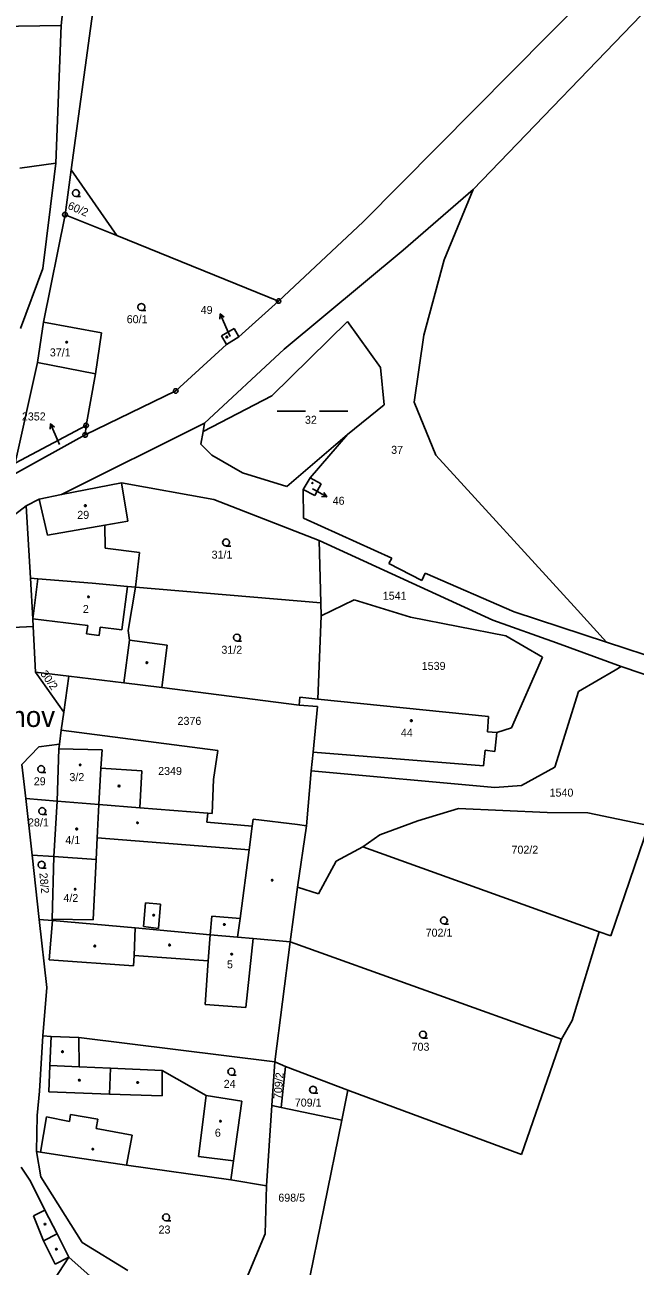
# Model space of a CAD drawing. Extents: x -852001 to -848657, y -1054973 to -1052182.
# Drawn here: x -850612.8 to -850483.1, y -1053593.3 to -1053329.6 of the extents above; entities that cross this region are included whole.
import ezdxf

# ---------------------------------------------------------------- set-up
doc = ezdxf.new("R2010")
doc.units = 0
for name, color, linetype in [('KN_HRANICE', 7, 'Continuous'), ('KN_KULTURY', 7, 'Continuous'), ('KN_MEZNIKY', 7, 'Continuous'), ('KN_PARCELY', 7, 'Continuous'), ('KN_SLUCKY', 7, 'Continuous'), ('KN_STAVEBNI', 7, 'Continuous')]:
    doc.layers.add(name, color=color, linetype=linetype)

# ---------------------------------------------------------------- blocks, each defined once
blk = doc.blocks.new('304')
blk.add_lwpolyline([(0, 0), (-0.38, 0.1), (-0.65, 0.37), (-0.75, 0.74), (-0.65, 1.11), (-0.38, 1.38), (-0.01, 1.48), (0.36, 1.38), (0.63, 1.11), (0.73, 0.73), (0.63, 0.35), (0.36, 0.08), (-0.02, -0.02), (0.98, -0.02)])
blk = doc.blocks.new('NAHRADNI_SYMBOL')
blk.add_lwpolyline([(0.09, 0.15), (0.18, 0), (0.09, -0.15), (-0.09, -0.15), (-0.18, 0), (-0.09, 0.15), (0.09, 0.15)])
blk = doc.blocks.new('803')
for p, q in [((-7.5, 0), (-1.5, 0)), ((1.5, 0), (7.5, 0))]:
    blk.add_line(p, q)
blk = doc.blocks.new('10292')
blk.add_line((0, 3), (0, 0))
blk.add_lwpolyline([(-0.5, 2), (0, 3), (0.5, 2)])
blk = doc.blocks.new('402')
blk.add_lwpolyline([(0.09, 0.15), (0.18, 0), (0.09, -0.15), (-0.09, -0.15), (-0.18, 0), (-0.09, 0.15), (0.09, 0.15)])
blk = doc.blocks.new('105')
blk.add_line((-0.12, 0), (0.12, 0))
blk.add_lwpolyline([(0.15, 0.48), (0.4, 0.3), (0.5, 0.01), (0.4, -0.28), (0.15, -0.46), (-0.16, -0.46), (-0.41, -0.28), (-0.51, 0.01), (-0.41, 0.3), (-0.16, 0.48), (0.15, 0.48)])

msp = doc.modelspace()

# ---------------------------------------------------------------- linework, layer by layer
at = {"layer": 'KN_HRANICE'}
for p, q in [((-850422.36, -1053251.92), (-850540.88, -1053371.46)), ((-850601.94, -1053301.5), (-850605.07, -1053329.74)), ((-850595.22, -1053304.04), (-850602.92, -1053360.4)), ((-850471.08, -1053316.39), (-850517.5, -1053364.63)), ((-850605.07, -1053329.74), (-850649.35, -1053330.52)), ((-850605.07, -1053329.74), (-850606.19, -1053358.98)), ((-850613.8, -1053360.1), (-850606.19, -1053358.98)), ((-850606.19, -1053358.98), (-850606.54, -1053361.94)), ((-850606.54, -1053361.94), (-850608.91, -1053381.35)), ((-850602.92, -1053360.4), (-850604.22, -1053369.95)), ((-850593.21, -1053374.4), (-850602.92, -1053360.4)), ((-850517.5, -1053364.63), (-850532.35, -1053377.48)), ((-850523.63, -1053379.54), (-850517.5, -1053364.63)), ((-850604.22, -1053369.95), (-850608.81, -1053392.78)), ((-850604.22, -1053369.95), (-850593.21, -1053374.4)), ((-850540.88, -1053371.46), (-850558.84, -1053388.31)), ((-850593.21, -1053374.4), (-850558.84, -1053388.31)), ((-850532.35, -1053377.48), (-850557.63, -1053398.49)), ((-850523.63, -1053379.54), (-850527.95, -1053395.53)), ((-850608.91, -1053381.35), (-850613.67, -1053394.11)), ((-850558.84, -1053388.31), (-850567.28, -1053395.9)), ((-850610.11, -1053401.34), (-850608.81, -1053392.78)), ((-850608.81, -1053392.78), (-850596.48, -1053395.02)), ((-850568.31, -1053394.11), (-850570.95, -1053395.69)), ((-850568.31, -1053394.11), (-850567.28, -1053395.9)), ((-850560.27, -1053408.43), (-850544.19, -1053392.62)), ((-850544.19, -1053392.62), (-850537.17, -1053402.39)), ((-850596.48, -1053395.02), (-850597.72, -1053403.77)), ((-850570.95, -1053395.69), (-850569.94, -1053397.53)), ((-850567.28, -1053395.9), (-850569.94, -1053397.53)), ((-850527.95, -1053395.53), (-850530.04, -1053409.8)), ((-850569.94, -1053397.53), (-850580.7, -1053407.38)), ((-850557.63, -1053398.49), (-850574.57, -1053414.22)), ((-850614.83, -1053422.71), (-850610.11, -1053401.34)), ((-850597.72, -1053403.77), (-850599.75, -1053414.73)), ((-850537.17, -1053402.39), (-850536.37, -1053410.3)), ((-850580.7, -1053407.38), (-850599.94, -1053416.73)), ((-850574.9, -1053416.03), (-850560.27, -1053408.43)), ((-850530.04, -1053409.8), (-850525.46, -1053421.02)), ((-850536.37, -1053410.3), (-850544.21, -1053416.61)), ((-850599.75, -1053414.73), (-850614.83, -1053422.71)), ((-850574.57, -1053414.22), (-850604.96, -1053429.4)), ((-850599.75, -1053414.73), (-850599.94, -1053416.73)), ((-850574.57, -1053414.22), (-850574.9, -1053416.03)), ((-850615.4, -1053425.29), (-850599.94, -1053416.73)), ((-850574.9, -1053416.03), (-850575.37, -1053418.66)), ((-850557.06, -1053427.7), (-850544.21, -1053416.61)), ((-850544.21, -1053416.61), (-850552.11, -1053425.85)), ((-850575.37, -1053418.66), (-850573.02, -1053421.04)), ((-850573.02, -1053421.04), (-850566.48, -1053424.79)), ((-850525.46, -1053421.02), (-850496.05, -1053453.17)), ((-850566.48, -1053424.79), (-850557.06, -1053427.7)), ((-850553.62, -1053428.28), (-850552.11, -1053425.85)), ((-850552.11, -1053425.85), (-850549.78, -1053427.12)), ((-850604.96, -1053429.4), (-850592.25, -1053426.9)), ((-850592.25, -1053426.9), (-850590.88, -1053435.07)), ((-850572.57, -1053430.44), (-850592.25, -1053426.9)), ((-850551.12, -1053429.62), (-850553.62, -1053428.28)), ((-850553.62, -1053428.28), (-850553.56, -1053434.38)), ((-850549.78, -1053427.12), (-850551.12, -1053429.62)), ((-850612.5, -1053431.79), (-850609.72, -1053430.34)), ((-850609.72, -1053430.34), (-850604.96, -1053429.4)), ((-850550.25, -1053439.12), (-850572.57, -1053430.44)), ((-850616.53, -1053434.88), (-850612.5, -1053431.79)), ((-850612.5, -1053431.79), (-850611.58, -1053447.13)), ((-850595.77, -1053435.91), (-850590.88, -1053435.07)), ((-850595.77, -1053435.91), (-850595.7, -1053440.8)), ((-850553.56, -1053434.38), (-850534.81, -1053442.92)), ((-850513.32, -1053456.08), (-850550.25, -1053439.12)), ((-850549.87, -1053452.39), (-850550.25, -1053439.12)), ((-850595.7, -1053440.8), (-850588.42, -1053441.72)), ((-850588.42, -1053441.72), (-850589.27, -1053449.03)), ((-850535.39, -1053444.01), (-850534.81, -1053442.92)), ((-850535.39, -1053444.01), (-850528.4, -1053447.62)), ((-850528.4, -1053447.62), (-850527.68, -1053446.11)), ((-850527.68, -1053446.11), (-850508.76, -1053454.28)), ((-850611.58, -1053447.13), (-850611.07, -1053455.75)), ((-850609.98, -1053447.27), (-850611.58, -1053447.13)), ((-850598.49, -1053448.24), (-850609.98, -1053447.27)), ((-850590.92, -1053448.89), (-850598.49, -1053448.24)), ((-850589.27, -1053449.03), (-850590.92, -1053448.89)), ((-850590.78, -1053458.28), (-850589.27, -1053449.03)), ((-850549.87, -1053452.39), (-850589.27, -1053449.03)), ((-850542.75, -1053451.78), (-850549.8, -1053455.11)), ((-850530.79, -1053455.44), (-850542.75, -1053451.78)), ((-850549.8, -1053455.11), (-850549.87, -1053452.39)), ((-850508.76, -1053454.28), (-850489.13, -1053460.73)), ((-850496.05, -1053453.17), (-850489.13, -1053460.73)), ((-850615.31, -1053457.61), (-850610.99, -1053457.38)), ((-850610.99, -1053457.38), (-850611.07, -1053455.75)), ((-850610.48, -1053467.11), (-850610.99, -1053457.38)), ((-850549.8, -1053455.11), (-850550.5, -1053472.85)), ((-850510.58, -1053459.38), (-850530.79, -1053455.44)), ((-850499.79, -1053460.85), (-850513.32, -1053456.08)), ((-850590.54, -1053460.32), (-850590.78, -1053458.28)), ((-850502.78, -1053463.9), (-850510.58, -1053459.38)), ((-850590.54, -1053460.32), (-850582.52, -1053461.36)), ((-850582.52, -1053461.36), (-850583.69, -1053470.39)), ((-850486.02, -1053465.93), (-850499.79, -1053460.85)), ((-850489.13, -1053460.73), (-850443.14, -1053475.85)), ((-850509.34, -1053478.96), (-850502.78, -1053463.9)), ((-850604.51, -1053475.57), (-850610.48, -1053467.11)), ((-850603.43, -1053467.94), (-850610.48, -1053467.11)), ((-850603.43, -1053467.94), (-850604.51, -1053475.57)), ((-850591.71, -1053469.37), (-850603.43, -1053467.94)), ((-850487.33, -1053466.69), (-850495.1, -1053471.21)), ((-850486.02, -1053465.93), (-850487.33, -1053466.69)), ((-850486.02, -1053465.93), (-850460.49, -1053474.58)), ((-850583.69, -1053470.39), (-850591.71, -1053469.37)), ((-850554.48, -1053474.15), (-850583.69, -1053470.39)), ((-850554.48, -1053474.15), (-850554.3, -1053472.43)), ((-850554.3, -1053472.43), (-850550.5, -1053472.85)), ((-850550.5, -1053472.85), (-850514.2, -1053476.51)), ((-850495.1, -1053471.21), (-850500.17, -1053487.31)), ((-850604.51, -1053475.57), (-850605.06, -1053479.44)), ((-850550.56, -1053474.4), (-850554.48, -1053474.15)), ((-850550.56, -1053474.4), (-850551.52, -1053484.07)), ((-850514.2, -1053476.51), (-850514.44, -1053479.78)), ((-850605.06, -1053479.44), (-850605.41, -1053482.4)), ((-850605.06, -1053479.44), (-850571.78, -1053483.77)), ((-850514.44, -1053479.78), (-850512.46, -1053479.93)), ((-850512.46, -1053479.93), (-850512.92, -1053483.93)), ((-850512.46, -1053479.93), (-850509.34, -1053478.96)), ((-850609.81, -1053482.98), (-850613.39, -1053486.7)), ((-850605.41, -1053482.4), (-850609.81, -1053482.98)), ((-850605.52, -1053483.37), (-850605.87, -1053494.49)), ((-850605.41, -1053482.4), (-850605.52, -1053483.37)), ((-850605.52, -1053483.37), (-850596.37, -1053483.61)), ((-850596.37, -1053483.61), (-850596.6, -1053487.53)), ((-850571.78, -1053483.77), (-850572.66, -1053489.9)), ((-850514.91, -1053483.7), (-850515.29, -1053487.01)), ((-850512.92, -1053483.93), (-850514.91, -1053483.7)), ((-850551.52, -1053484.07), (-850551.93, -1053488.05)), ((-850551.52, -1053484.07), (-850515.29, -1053487.01)), ((-850613.39, -1053486.7), (-850612.58, -1053493.95)), ((-850596.6, -1053487.53), (-850587.87, -1053488.04)), ((-850588.33, -1053495.91), (-850587.87, -1053488.04)), ((-850551.93, -1053488.05), (-850552.89, -1053499.71)), ((-850512.86, -1053491.6), (-850551.93, -1053488.05)), ((-850500.17, -1053487.31), (-850507.22, -1053491.2)), ((-850572.66, -1053489.9), (-850572.94, -1053497.11)), ((-850507.22, -1053491.2), (-850512.86, -1053491.6)), ((-850605.87, -1053494.49), (-850612.58, -1053493.95)), ((-850612.58, -1053493.95), (-850611.23, -1053505.98)), ((-850605.87, -1053494.49), (-850606.64, -1053506.28)), ((-850597.02, -1053495.21), (-850605.87, -1053494.49)), ((-850597.02, -1053495.21), (-850588.33, -1053495.91)), ((-850588.33, -1053495.91), (-850573.91, -1053497.08)), ((-850573.91, -1053497.08), (-850574.07, -1053498.98)), ((-850572.94, -1053497.11), (-850573.91, -1053497.08)), ((-850520.64, -1053496.07), (-850529.27, -1053498.69)), ((-850501.73, -1053496.94), (-850520.64, -1053496.07)), ((-850493.13, -1053497), (-850501.73, -1053496.94)), ((-850480.2, -1053499.68), (-850493.13, -1053497)), ((-850574.07, -1053498.98), (-850564.43, -1053499.83)), ((-850564.28, -1053498.36), (-850564.43, -1053499.83)), ((-850564.28, -1053498.36), (-850554.83, -1053499.43)), ((-850554.83, -1053499.43), (-850552.89, -1053499.71)), ((-850552.89, -1053499.71), (-850554.83, -1053512.79)), ((-850529.27, -1053498.69), (-850537.35, -1053501.64)), ((-850488.23, -1053523.1), (-850480.2, -1053499.68)), ((-850537.35, -1053501.64), (-850540.97, -1053504.23)), ((-850540.97, -1053504.23), (-850546.58, -1053507.26)), ((-850540.97, -1053504.23), (-850490.71, -1053522.25)), ((-850611.23, -1053505.98), (-850609.7, -1053519.63)), ((-850611.23, -1053505.98), (-850606.64, -1053506.28)), ((-850606.64, -1053506.28), (-850606.98, -1053519.55)), ((-850597.6, -1053506.87), (-850606.64, -1053506.28)), ((-850598.23, -1053519.71), (-850597.6, -1053506.87)), ((-850546.58, -1053507.26), (-850550.37, -1053514.19)), ((-850554.83, -1053512.79), (-850556.37, -1053524.38)), ((-850554.83, -1053512.79), (-850550.37, -1053514.19)), ((-850609.7, -1053519.63), (-850606.88, -1053519.88)), ((-850609.7, -1053519.63), (-850608.08, -1053534.07)), ((-850606.98, -1053519.55), (-850606.88, -1053519.88)), ((-850606.98, -1053519.55), (-850598.23, -1053519.71)), ((-850606.88, -1053519.88), (-850589.35, -1053521.44)), ((-850589.35, -1053521.44), (-850573.38, -1053522.86)), ((-850573.38, -1053522.86), (-850567.55, -1053523.38)), ((-850567.55, -1053523.38), (-850564.24, -1053523.67)), ((-850490.71, -1053522.25), (-850496.45, -1053541.11)), ((-850490.71, -1053522.25), (-850488.23, -1053523.1)), ((-850564.24, -1053523.67), (-850556.37, -1053524.38)), ((-850556.37, -1053524.38), (-850559.65, -1053549.88)), ((-850498.75, -1053545.06), (-850556.37, -1053524.38)), ((-850608.92, -1053544.34), (-850608.08, -1053534.07)), ((-850496.45, -1053541.11), (-850498.75, -1053545.06)), ((-850608.92, -1053544.34), (-850609.68, -1053556.12)), ((-850607.17, -1053544.47), (-850608.92, -1053544.34)), ((-850601.28, -1053544.72), (-850607.17, -1053544.47)), ((-850559.65, -1053549.88), (-850601.28, -1053544.72)), ((-850601.25, -1053550.93), (-850601.28, -1053544.72)), ((-850498.75, -1053545.06), (-850507.22, -1053569.51)), ((-850601.25, -1053550.93), (-850594.55, -1053551.21)), ((-850594.55, -1053551.21), (-850583.56, -1053551.68)), ((-850583.56, -1053551.68), (-850574.24, -1053556.99)), ((-850559.65, -1053549.88), (-850560.28, -1053559.12)), ((-850557.34, -1053550.88), (-850559.65, -1053549.88)), ((-850558.27, -1053559.54), (-850557.34, -1053550.88)), ((-850557.34, -1053550.88), (-850544.12, -1053555.88)), ((-850609.68, -1053556.12), (-850610.14, -1053561.27)), ((-850574.24, -1053556.99), (-850566.62, -1053558.23)), ((-850544.12, -1053555.88), (-850545.42, -1053562.28)), ((-850507.22, -1053569.51), (-850544.12, -1053555.88)), ((-850566.62, -1053558.23), (-850568.43, -1053570.88)), ((-850560.28, -1053559.12), (-850561.44, -1053576.17)), ((-850560.28, -1053559.12), (-850558.27, -1053559.54)), ((-850545.42, -1053562.28), (-850558.27, -1053559.54)), ((-850610.32, -1053568.9), (-850610.14, -1053561.27)), ((-850545.42, -1053562.28), (-850552.92, -1053599.08)), ((-850610.32, -1053568.9), (-850609.43, -1053569.03)), ((-850610.32, -1053568.9), (-850609.38, -1053574.28)), ((-850603.51, -1053570), (-850609.43, -1053569.03)), ((-850591.16, -1053571.79), (-850603.51, -1053570)), ((-850568.43, -1053570.88), (-850569, -1053574.9)), ((-850613.54, -1053572.2), (-850611.6, -1053575.23)), ((-850591.16, -1053571.79), (-850569, -1053574.9)), ((-850611.6, -1053575.23), (-850608.5, -1053581.34)), ((-850609.38, -1053574.28), (-850600.56, -1053588.2)), ((-850569, -1053574.9), (-850561.44, -1053576.17)), ((-850561.72, -1053586.38), (-850561.44, -1053576.17)), ((-850608.5, -1053581.34), (-850605.92, -1053586.42)), ((-850605.92, -1053586.42), (-850603.43, -1053591.33)), ((-850565.66, -1053595.86), (-850561.72, -1053586.38)), ((-850600.56, -1053588.2), (-850590.91, -1053594.16)), ((-850597.64, -1053596.49), (-850603.43, -1053591.33))]:
    msp.add_line(p, q, dxfattribs=at)
at = {"layer": 'KN_PARCELY'}
for p, q in [((-850569.11, -1053395.83), (-850570.03, -1053393.77)), ((-850605.41, -1053418.73), (-850606.12, -1053417.12)), ((-850551.63, -1053428.18), (-850551.22, -1053428.41))]:
    msp.add_line(p, q, dxfattribs=at)
at = {"layer": 'KN_SLUCKY'}
for p, q in [((-850597.72, -1053403.77), (-850610.11, -1053401.34)), ((-850607.95, -1053438), (-850609.72, -1053430.34)), ((-850607.95, -1053438), (-850595.77, -1053435.91)), ((-850611.07, -1053455.75), (-850609.98, -1053447.27)), ((-850592.14, -1053458.14), (-850590.92, -1053448.89)), ((-850611.07, -1053455.75), (-850599.4, -1053457.2)), ((-850599.4, -1053457.2), (-850599.64, -1053458.96)), ((-850596.96, -1053459.31), (-850596.73, -1053457.54)), ((-850596.73, -1053457.54), (-850592.14, -1053458.14)), ((-850599.64, -1053458.96), (-850596.96, -1053459.31)), ((-850591.71, -1053469.37), (-850590.54, -1053460.32)), ((-850596.6, -1053487.53), (-850597.02, -1053495.21)), ((-850597.02, -1053495.21), (-850597.37, -1053502.28)), ((-850597.37, -1053502.28), (-850597.6, -1053506.87)), ((-850565.06, -1053504.83), (-850597.37, -1053502.28)), ((-850565.06, -1053504.83), (-850564.43, -1053499.83)), ((-850567, -1053519.43), (-850565.06, -1053504.83)), ((-850587.53, -1053521.15), (-850587.13, -1053516.08)), ((-850587.13, -1053516.08), (-850583.93, -1053516.41)), ((-850583.93, -1053516.41), (-850584.33, -1053521.55)), ((-850607.6, -1053528.17), (-850606.88, -1053519.88)), ((-850573.03, -1053518.9), (-850573.38, -1053522.86)), ((-850567, -1053519.43), (-850573.03, -1053518.9)), ((-850567.55, -1053523.38), (-850567, -1053519.43)), ((-850589.35, -1053521.44), (-850589.51, -1053527.26)), ((-850584.33, -1053521.55), (-850587.53, -1053521.15)), ((-850573.79, -1053528.43), (-850573.38, -1053522.86)), ((-850564.24, -1053523.67), (-850565.81, -1053538.34)), ((-850607.6, -1053528.17), (-850589.68, -1053529.5)), ((-850589.51, -1053527.26), (-850589.68, -1053529.5)), ((-850589.51, -1053527.26), (-850573.79, -1053528.43)), ((-850573.79, -1053528.43), (-850574.48, -1053537.7)), ((-850565.81, -1053538.34), (-850574.48, -1053537.7)), ((-850607.17, -1053544.47), (-850607.44, -1053550.66)), ((-850607.68, -1053556.25), (-850607.44, -1053550.66)), ((-850607.44, -1053550.66), (-850601.25, -1053550.93)), ((-850594.76, -1053556.72), (-850594.55, -1053551.21)), ((-850583.58, -1053557.1), (-850583.56, -1053551.68)), ((-850594.76, -1053556.72), (-850607.68, -1053556.25)), ((-850594.76, -1053556.72), (-850583.58, -1053557.1)), ((-850575.86, -1053569.95), (-850574.24, -1053556.99)), ((-850609.43, -1053569.03), (-850608.15, -1053561.53)), ((-850608.15, -1053561.53), (-850603.3, -1053562.53)), ((-850603.3, -1053562.53), (-850603.04, -1053561.02)), ((-850603.04, -1053561.02), (-850597.26, -1053562.05)), ((-850597.6, -1053564.03), (-850597.26, -1053562.05)), ((-850597.6, -1053564.03), (-850589.93, -1053565.41)), ((-850589.93, -1053565.41), (-850591.16, -1053571.79)), ((-850568.43, -1053570.88), (-850575.86, -1053569.95)), ((-850610.91, -1053582.56), (-850608.5, -1053581.34)), ((-850608.82, -1053587.9), (-850610.91, -1053582.56)), ((-850608.82, -1053587.9), (-850605.92, -1053586.42)), ((-850606.33, -1053592.8), (-850608.82, -1053587.9)), ((-850603.43, -1053591.33), (-850612.02, -1053604.55)), ((-850603.43, -1053591.33), (-850606.33, -1053592.8))]:
    msp.add_line(p, q, dxfattribs=at)
at = {"layer": 'KN_STAVEBNI'}
for p, q in [((-850610.11, -1053401.34), (-850608.81, -1053392.78)), ((-850608.81, -1053392.78), (-850596.48, -1053395.02)), ((-850568.31, -1053394.11), (-850570.95, -1053395.69)), ((-850568.31, -1053394.11), (-850567.28, -1053395.9)), ((-850596.48, -1053395.02), (-850597.72, -1053403.77)), ((-850570.95, -1053395.69), (-850569.94, -1053397.53)), ((-850567.28, -1053395.9), (-850569.94, -1053397.53)), ((-850597.72, -1053403.77), (-850610.11, -1053401.34)), ((-850553.62, -1053428.28), (-850552.11, -1053425.85)), ((-850552.11, -1053425.85), (-850549.78, -1053427.12)), ((-850604.96, -1053429.4), (-850592.25, -1053426.9)), ((-850592.25, -1053426.9), (-850590.88, -1053435.07)), ((-850551.12, -1053429.62), (-850553.62, -1053428.28)), ((-850549.78, -1053427.12), (-850551.12, -1053429.62)), ((-850609.72, -1053430.34), (-850604.96, -1053429.4)), ((-850607.95, -1053438), (-850609.72, -1053430.34)), ((-850607.95, -1053438), (-850595.77, -1053435.91)), ((-850595.77, -1053435.91), (-850590.88, -1053435.07)), ((-850611.07, -1053455.75), (-850609.98, -1053447.27)), ((-850598.49, -1053448.24), (-850609.98, -1053447.27)), ((-850590.92, -1053448.89), (-850598.49, -1053448.24)), ((-850592.14, -1053458.14), (-850590.92, -1053448.89)), ((-850611.07, -1053455.75), (-850599.4, -1053457.2)), ((-850599.4, -1053457.2), (-850599.64, -1053458.96)), ((-850596.96, -1053459.31), (-850596.73, -1053457.54)), ((-850596.73, -1053457.54), (-850592.14, -1053458.14)), ((-850599.64, -1053458.96), (-850596.96, -1053459.31)), ((-850554.48, -1053474.15), (-850554.3, -1053472.43)), ((-850554.3, -1053472.43), (-850550.5, -1053472.85)), ((-850550.5, -1053472.85), (-850514.2, -1053476.51)), ((-850550.56, -1053474.4), (-850554.48, -1053474.15)), ((-850550.56, -1053474.4), (-850551.52, -1053484.07)), ((-850514.2, -1053476.51), (-850514.44, -1053479.78)), ((-850514.44, -1053479.78), (-850512.46, -1053479.93)), ((-850512.46, -1053479.93), (-850512.92, -1053483.93)), ((-850605.52, -1053483.37), (-850605.87, -1053494.49)), ((-850605.52, -1053483.37), (-850596.37, -1053483.61)), ((-850596.37, -1053483.61), (-850596.6, -1053487.53)), ((-850514.91, -1053483.7), (-850515.29, -1053487.01)), ((-850512.92, -1053483.93), (-850514.91, -1053483.7)), ((-850551.52, -1053484.07), (-850515.29, -1053487.01)), ((-850596.6, -1053487.53), (-850597.02, -1053495.21)), ((-850605.87, -1053494.49), (-850606.64, -1053506.28)), ((-850597.02, -1053495.21), (-850605.87, -1053494.49)), ((-850597.02, -1053495.21), (-850605.87, -1053494.49)), ((-850597.02, -1053495.21), (-850597.37, -1053502.28)), ((-850597.37, -1053502.28), (-850597.6, -1053506.87)), ((-850597.6, -1053506.87), (-850606.64, -1053506.28)), ((-850573.79, -1053528.43), (-850573.38, -1053522.86)), ((-850573.38, -1053522.86), (-850567.55, -1053523.38)), ((-850567.55, -1053523.38), (-850564.24, -1053523.67)), ((-850564.24, -1053523.67), (-850565.81, -1053538.34)), ((-850573.79, -1053528.43), (-850574.48, -1053537.7)), ((-850565.81, -1053538.34), (-850574.48, -1053537.7)), ((-850575.86, -1053569.95), (-850574.24, -1053556.99)), ((-850574.24, -1053556.99), (-850566.62, -1053558.23)), ((-850566.62, -1053558.23), (-850568.43, -1053570.88)), ((-850568.43, -1053570.88), (-850575.86, -1053569.95))]:
    msp.add_line(p, q, dxfattribs=at)

# ---------------------------------------------------------------- block references
at = {"layer": 'KN_KULTURY'}
for name, p in [('304', (-850601.9, -1053366.1)), ('304', (-850588, -1053390.3)), ('402', (-850603.89, -1053397.04)), ('402', (-850569.84, -1053395.92)), ('803', (-850551.62, -1053411.66)), ('402', (-850599.91, -1053431.74)), ('304', (-850570, -1053440.3)), ('402', (-850599.25, -1053451.1)), ('304', (-850567.68, -1053460.5)), ('402', (-850586.83, -1053465.09)), ('402', (-850530.63, -1053477.41)), ('304', (-850609.29, -1053488.43)), ('402', (-850601.01, -1053486.8)), ('402', (-850592.74, -1053491.28)), ('304', (-850609.06, -1053497.35)), ('402', (-850588.84, -1053499.09)), ('402', (-850601.75, -1053500.42)), ('304', (-850609.19, -1053508.74)), ('402', (-850560.2, -1053511.29)), ('NAHRADNI_SYMBOL', (-850602.06, -1053513.21)), ('402', (-850585.4, -1053518.73)), ('402', (-850570.36, -1053520.69)), ('304', (-850523.7, -1053520.58)), ('402', (-850597.91, -1053525.26)), ('402', (-850582.02, -1053525.05)), ('402', (-850568.81, -1053526.98)), ('304', (-850528.15, -1053544.81)), ('402', (-850604.78, -1053547.7)), ('304', (-850568.85, -1053552.69)), ('402', (-850601.17, -1053553.76)), ('402', (-850588.78, -1053554.26)), ('304', (-850551.51, -1053556.53)), ('402', (-850571.19, -1053562.47)), ('402', (-850598.32, -1053568.4)), ('304', (-850582.73, -1053583.63)), ('402', (-850608.49, -1053584.36)), ('402', (-850606.06, -1053589.67))]:
    msp.add_blockref(name, p, dxfattribs=at)
at = {"layer": 'KN_KULTURY', "xscale": 0.67, "yscale": 0.67}
msp.add_blockref('402', (-850551.67, -1053426.93), dxfattribs=at)
at = {"layer": 'KN_MEZNIKY'}
for p in [(-850604.22, -1053369.95), (-850558.84, -1053388.31), (-850580.7, -1053407.38), (-850599.75, -1053414.73), (-850599.94, -1053416.73)]:
    msp.add_blockref('105', p, dxfattribs=at)
at = {"layer": 'KN_PARCELY'}
for p, rotation in [((-850570.03, -1053393.77), 24.006932), ((-850606.12, -1053417.12), 23.663157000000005), ((-850551.22, -1053428.41), -118.78476800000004)]:
    msp.add_blockref('10292', p, dxfattribs=dict(at, rotation=rotation))

# ---------------------------------------------------------------- texts
for s, height, rotation, p in [('60/2', 1.7, 336.498, (-850603.8, -1053368.64)), ('2352', 0.1, 26.356, (-850605.58, -1053418.81)), ('30/2', 1.7, 305.157, (-850609.56, -1053467.45)), ('28/2', 1.7, 275.364, (-850609.68, -1053509.8)), ('709/2', 1.7, 84.798, (-850558.27, -1053557.85))]:
    msp.add_text(s, height=height, rotation=rotation, dxfattribs=at).set_placement(p)
for s, height, p in [('60/1', 1.7, (-850591.12, -1053393)), ('49', 1.7, (-850575.4, -1053391.03)), ('49', 0.1, (-850569.2, -1053395.83)), ('37/1', 1.7, (-850607.46, -1053400.05)), ('2352', 1.7, (-850613.4, -1053413.65)), ('32', 1.7, (-850553.24, -1053414.36)), ('37', 1.7, (-850534.92, -1053420.74)), ('46', 0.1, (-850551.73, -1053428.18)), ('46', 1.7, (-850547.35, -1053431.55)), ('29', 1.7, (-850601.63, -1053434.55)), ('31/1', 1.7, (-850573.08, -1053443)), ('1541', 1.7, (-850536.7, -1053451.72)), ('2', 1.7, (-850600.44, -1053454.54)), ('31/2', 1.7, (-850571, -1053463.2)), ('1539', 1.7, (-850528.42, -1053466.63)), ('Strahov', 4.4, (-850626.63, -1053478.74)), ('2376', 1.7, (-850580.32, -1053478.3)), ('44', 1.7, (-850532.85, -1053480.8)), ('3/2', 1.7, (-850603.3, -1053490.25)), ('2349', 1.7, (-850584.44, -1053488.94)), ('29', 1.7, (-850610.87, -1053491.13)), ('1540', 1.7, (-850501.25, -1053493.54)), ('28/1', 1.7, (-850612.09, -1053499.87)), ('4/1', 1.7, (-850604.17, -1053503.62)), ('702/2', 1.7, (-850509.35, -1053505.66)), ('4/2', 1.7, (-850604.57, -1053515.91)), ('702/1', 1.7, (-850527.59, -1053523.28)), ('5', 1.7, (-850569.81, -1053530)), ('703', 1.7, (-850530.58, -1053547.51)), ('24', 1.7, (-850570.51, -1053555.39)), ('709/1', 1.7, (-850555.4, -1053559.37)), ('6', 1.7, (-850572.39, -1053565.77)), ('698/5', 1.7, (-850558.9, -1053579.56)), ('23', 1.7, (-850584.35, -1053586.33))]:
    msp.add_text(s, height=height, dxfattribs=at).set_placement(p)

doc.saveas('drawing.dxf')
